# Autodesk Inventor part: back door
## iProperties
Author: vincent molino
Shininess: 20.0
Angle Display Precision: 2
Document Length Units: 11272
Document Angle Units: 11286
Document Time Units: 11279
Document Mass Units: 11290
Document Length Units Precision: 3
Document Angle Units Precision: 2
Compacted: True
PropertySet Name: _Private Model Information
Created: 2002-01
Part Number: back door
Document SubType Name: Modeling
Designer: vincent molino
Control State: 0
Master: False
Checked Out: False
PropertySet Name: Design Tracking Control
Density: 0.0
Volumn: 0.0
Area: 0.0
PropertySet Name: Model Information
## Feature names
1. Extrusion1
2. Fillet1
